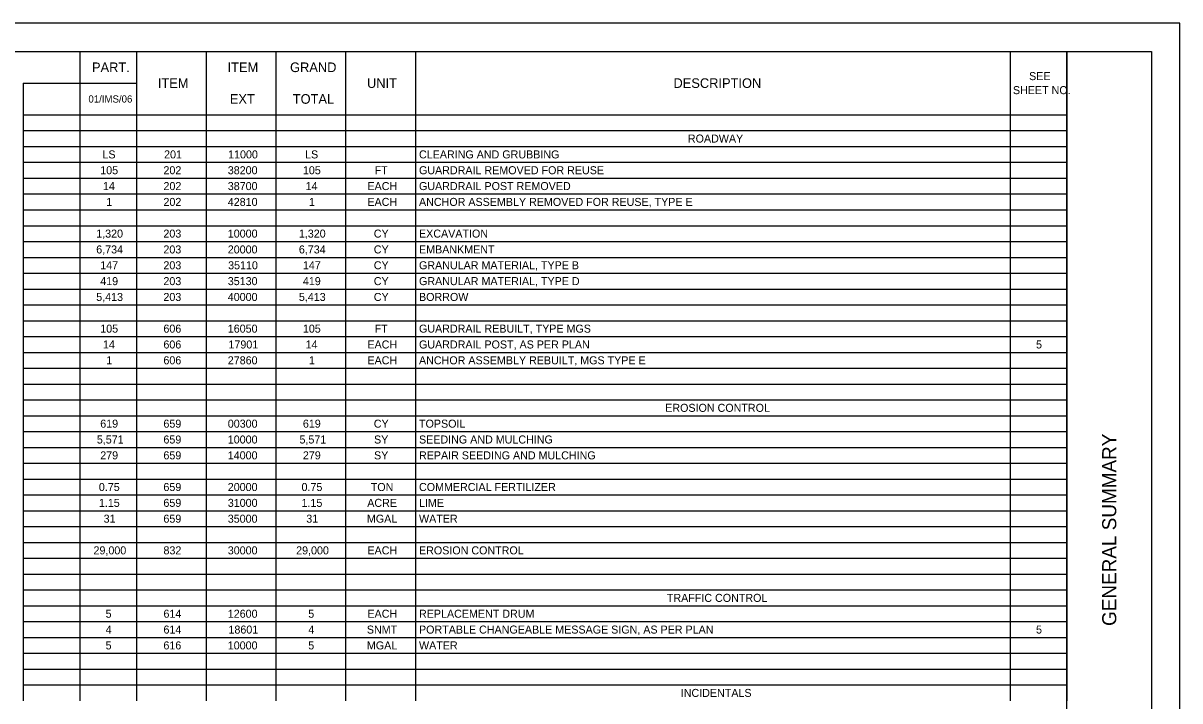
# Model space of a CAD drawing. Extents: x 0 to 34, y 0 to 22.
# Drawn here: x 13.53 to 34, y 10.02 to 22 of the extents above; entities that cross this region are included whole.
import ezdxf

# ---------------------------------------------------------------- set-up
doc = ezdxf.new("R2010")
doc.units = 0
for name, color, linetype in [('Default', 7, 'Continuous'), ('SH_Border', 7, 'Continuous'), ('SH_Cut_Line', 7, 'Continuous'), ('SH_Data', 7, 'Continuous')]:
    doc.layers.add(name, color=color, linetype=linetype)

msp = doc.modelspace()

# ---------------------------------------------------------------- linework, layer by layer
at = {"layer": 'Default'}
for p, q in [((13.531, 21.5), (15.536, 21.5)), ((14.533, 21.5), (14.533, 21.22)), ((15.536, 21.5), (32.001, 21.5)), ((15.536, 21.5), (15.536, 21.22)), ((16.77, 21.5), (16.77, 21.22)), ((18.004, 21.5), (18.004, 21.22)), ((19.237, 21.5), (19.237, 21.22)), ((20.471, 21.5), (20.471, 21.22)), ((30.998, 21.5), (30.998, 21.22)), ((32.001, 21.5), (32.001, 21.22)), ((14.533, 21.22), (14.533, 20.94)), ((15.536, 21.22), (15.536, 20.94)), ((16.77, 21.22), (16.77, 20.94)), ((18.004, 21.22), (18.004, 20.94)), ((19.237, 21.22), (19.237, 20.94)), ((20.471, 21.22), (20.471, 20.94)), ((30.998, 21.22), (30.998, 20.94)), ((32.001, 21.22), (32.001, 20.94)), ((13.531, 20.94), (15.536, 20.94)), ((13.531, 20.94), (13.531, 20.66)), ((14.533, 20.94), (14.533, 20.66)), ((15.536, 20.94), (15.536, 20.66)), ((16.77, 20.94), (16.77, 20.66)), ((18.004, 20.94), (18.004, 20.66)), ((19.237, 20.94), (19.237, 20.66)), ((20.471, 20.94), (20.471, 20.66)), ((30.998, 20.94), (30.998, 20.66)), ((32.001, 20.94), (32.001, 20.66)), ((13.531, 20.66), (13.531, 20.38)), ((14.533, 20.66), (14.533, 20.38)), ((15.536, 20.66), (15.536, 20.38)), ((16.77, 20.66), (16.77, 20.38)), ((18.004, 20.66), (18.004, 20.38)), ((19.237, 20.66), (19.237, 20.38)), ((20.471, 20.66), (20.471, 20.38)), ((30.998, 20.66), (30.998, 20.38)), ((32.001, 20.66), (32.001, 20.38)), ((13.531, 20.38), (15.536, 20.38)), ((13.531, 20.38), (13.531, 20.1)), ((14.533, 20.38), (14.533, 20.1)), ((15.536, 20.38), (32.001, 20.38)), ((15.536, 20.38), (15.536, 20.1)), ((16.77, 20.38), (16.77, 20.1)), ((18.004, 20.38), (18.004, 20.1)), ((19.237, 20.38), (19.237, 20.1)), ((20.471, 20.38), (20.471, 20.1)), ((30.998, 20.38), (30.998, 20.1)), ((32.001, 20.38), (32.001, 20.1)), ((13.531, 20.1), (15.536, 20.1)), ((13.531, 20.1), (13.531, 18.7)), ((14.533, 20.1), (14.533, 18.7)), ((15.536, 20.1), (32.001, 20.1)), ((15.536, 20.1), (15.536, 18.7)), ((16.77, 20.1), (16.77, 18.7)), ((18.004, 20.1), (18.004, 18.7)), ((19.237, 20.1), (19.237, 18.7)), ((20.471, 20.1), (20.471, 18.7)), ((30.998, 20.1), (30.998, 18.7)), ((32.001, 20.1), (32.001, 18.7)), ((13.531, 19.82), (15.536, 19.82)), ((15.536, 19.82), (32.001, 19.82)), ((13.531, 19.54), (15.536, 19.54)), ((15.536, 19.54), (32.001, 19.54)), ((13.531, 19.26), (15.536, 19.26)), ((15.536, 19.26), (32.001, 19.26)), ((13.531, 18.98), (15.536, 18.98)), ((15.536, 18.98), (32.001, 18.98)), ((13.531, 18.7), (15.536, 18.7)), ((13.531, 18.7), (13.531, 18.14)), ((14.533, 18.7), (14.533, 18.14)), ((15.536, 18.7), (32.001, 18.7)), ((15.536, 18.7), (15.536, 18.14)), ((16.77, 18.7), (16.77, 18.14)), ((18.004, 18.7), (18.004, 18.14)), ((19.237, 18.7), (19.237, 18.14)), ((20.471, 18.7), (20.471, 18.14)), ((30.998, 18.7), (30.998, 18.14)), ((32.001, 18.7), (32.001, 18.14)), ((13.531, 18.42), (15.536, 18.42)), ((15.536, 18.42), (32.001, 18.42)), ((13.531, 18.14), (15.536, 18.14)), ((13.531, 18.14), (13.531, 17.86)), ((14.533, 18.14), (14.533, 17.86)), ((15.536, 18.14), (32.001, 18.14)), ((15.536, 18.14), (15.536, 17.86)), ((16.77, 18.14), (16.77, 17.86)), ((18.004, 18.14), (18.004, 17.86)), ((19.237, 18.14), (19.237, 17.86)), ((20.471, 18.14), (20.471, 17.86)), ((30.998, 18.14), (30.998, 17.86)), ((32.001, 18.14), (32.001, 17.86)), ((13.531, 17.86), (15.536, 17.86)), ((13.531, 17.86), (13.531, 17.58)), ((14.533, 17.86), (14.533, 17.58)), ((15.536, 17.86), (32.001, 17.86)), ((15.536, 17.86), (15.536, 17.58)), ((16.77, 17.86), (16.77, 17.58)), ((18.004, 17.86), (18.004, 17.58)), ((19.237, 17.86), (19.237, 17.58)), ((20.471, 17.86), (20.471, 17.58)), ((30.998, 17.86), (30.998, 17.58)), ((32.001, 17.86), (32.001, 17.58)), ((13.531, 17.58), (15.536, 17.58)), ((13.531, 17.58), (13.531, 17.3)), ((14.533, 17.58), (14.533, 17.3)), ((15.536, 17.58), (32.001, 17.58)), ((15.536, 17.58), (15.536, 17.3)), ((16.77, 17.58), (16.77, 17.3)), ((18.004, 17.58), (18.004, 17.3)), ((19.237, 17.58), (19.237, 17.3)), ((20.471, 17.58), (20.471, 17.3)), ((30.998, 17.58), (30.998, 17.3)), ((32.001, 17.58), (32.001, 17.3)), ((13.531, 17.3), (15.536, 17.3)), ((13.531, 17.3), (13.531, 17.02)), ((14.533, 17.3), (14.533, 17.02)), ((15.536, 17.3), (32.001, 17.3)), ((15.536, 17.3), (15.536, 17.02)), ((16.77, 17.3), (16.77, 17.02)), ((18.004, 17.3), (18.004, 17.02)), ((19.237, 17.3), (19.237, 17.02)), ((20.471, 17.3), (20.471, 17.02)), ((30.998, 17.3), (30.998, 17.02)), ((32.001, 17.3), (32.001, 17.02)), ((13.531, 17.02), (15.536, 17.02)), ((13.531, 17.02), (13.531, 16.74)), ((14.533, 17.02), (14.533, 16.74)), ((15.536, 17.02), (32.001, 17.02)), ((15.536, 17.02), (15.536, 16.74)), ((16.77, 17.02), (16.77, 16.74)), ((18.004, 17.02), (18.004, 16.74)), ((19.237, 17.02), (19.237, 16.74)), ((20.471, 17.02), (20.471, 16.74)), ((30.998, 17.02), (30.998, 16.74)), ((32.001, 17.02), (32.001, 16.74)), ((13.531, 16.74), (15.536, 16.74)), ((13.531, 16.74), (13.531, 16.18)), ((14.533, 16.74), (14.533, 16.18)), ((15.536, 16.74), (32.001, 16.74)), ((15.536, 16.74), (15.536, 16.18)), ((16.77, 16.74), (16.77, 16.18)), ((18.004, 16.74), (18.004, 16.18)), ((19.237, 16.74), (19.237, 16.18)), ((20.471, 16.74), (20.471, 16.18)), ((30.998, 16.74), (30.998, 16.18)), ((32.001, 16.74), (32.001, 16.18)), ((13.531, 16.46), (15.536, 16.46)), ((15.536, 16.46), (32.001, 16.46)), ((13.531, 16.18), (15.536, 16.18)), ((13.531, 16.18), (13.531, 15.9)), ((14.533, 16.18), (14.533, 15.9)), ((15.536, 16.18), (32.001, 16.18)), ((15.536, 16.18), (15.536, 15.9)), ((16.77, 16.18), (16.77, 15.9)), ((18.004, 16.18), (18.004, 15.9)), ((19.237, 16.18), (19.237, 15.9)), ((20.471, 16.18), (20.471, 15.9)), ((30.998, 16.18), (30.998, 15.9)), ((32.001, 16.18), (32.001, 15.9)), ((13.531, 15.9), (15.536, 15.9)), ((13.531, 15.9), (13.531, 15.62)), ((14.533, 15.9), (14.533, 15.62)), ((15.536, 15.9), (32.001, 15.9)), ((15.536, 15.9), (15.536, 15.62)), ((16.77, 15.9), (16.77, 15.62)), ((18.004, 15.9), (18.004, 15.62)), ((19.237, 15.9), (19.237, 15.62)), ((20.471, 15.9), (20.471, 15.62)), ((30.998, 15.9), (30.998, 15.62)), ((32.001, 15.9), (32.001, 15.62)), ((13.531, 15.62), (15.536, 15.62)), ((13.531, 15.62), (13.531, 15.34)), ((14.533, 15.62), (14.533, 15.34)), ((15.536, 15.62), (32.001, 15.62)), ((15.536, 15.62), (15.536, 15.34)), ((16.77, 15.62), (16.77, 15.34)), ((18.004, 15.62), (18.004, 15.34)), ((19.237, 15.62), (19.237, 15.34)), ((20.471, 15.62), (20.471, 15.34)), ((30.998, 15.62), (30.998, 15.34)), ((32.001, 15.62), (32.001, 15.34)), ((13.531, 15.34), (15.536, 15.34)), ((13.531, 15.34), (13.531, 14.78)), ((14.533, 15.34), (14.533, 14.78)), ((15.536, 15.34), (32.001, 15.34)), ((15.536, 15.34), (15.536, 14.78)), ((16.77, 15.34), (16.77, 14.78)), ((18.004, 15.34), (18.004, 14.78)), ((19.237, 15.34), (19.237, 14.78)), ((20.471, 15.34), (20.471, 14.78)), ((30.998, 15.34), (30.998, 14.78)), ((32.001, 15.34), (32.001, 14.78)), ((13.531, 15.06), (15.536, 15.06)), ((15.536, 15.06), (32.001, 15.06)), ((13.531, 14.78), (15.536, 14.78)), ((13.531, 14.78), (13.531, 14.5)), ((14.533, 14.78), (14.533, 14.5)), ((15.536, 14.78), (32.001, 14.78)), ((15.536, 14.78), (15.536, 14.5)), ((16.77, 14.78), (16.77, 14.5)), ((18.004, 14.78), (18.004, 14.5)), ((19.237, 14.78), (19.237, 14.5)), ((20.471, 14.78), (20.471, 14.5)), ((30.998, 14.78), (30.998, 14.5)), ((32.001, 14.78), (32.001, 14.5)), ((13.531, 14.5), (15.536, 14.5)), ((13.531, 14.5), (13.531, 14.22)), ((14.533, 14.5), (14.533, 14.22)), ((15.536, 14.5), (32.001, 14.5)), ((15.536, 14.5), (15.536, 14.22)), ((16.77, 14.5), (16.77, 14.22)), ((18.004, 14.5), (18.004, 14.22)), ((19.237, 14.5), (19.237, 14.22)), ((20.471, 14.5), (20.471, 14.22)), ((30.998, 14.5), (30.998, 14.22)), ((32.001, 14.5), (32.001, 14.22)), ((13.531, 14.22), (15.536, 14.22)), ((13.531, 14.22), (13.531, 13.94)), ((14.533, 14.22), (14.533, 13.94)), ((15.536, 14.22), (32.001, 14.22)), ((15.536, 14.22), (15.536, 13.94)), ((16.77, 14.22), (16.77, 13.94)), ((18.004, 14.22), (18.004, 13.94)), ((19.237, 14.22), (19.237, 13.94)), ((20.471, 14.22), (20.471, 13.94)), ((30.998, 14.22), (30.998, 13.94)), ((32.001, 14.22), (32.001, 13.94)), ((13.531, 13.94), (15.536, 13.94)), ((13.531, 13.94), (13.531, 11.7)), ((14.533, 13.94), (14.533, 11.7)), ((15.536, 13.94), (32.001, 13.94)), ((15.536, 13.94), (15.536, 11.7)), ((16.77, 13.94), (16.77, 11.7)), ((18.004, 13.94), (18.004, 11.7)), ((19.237, 13.94), (19.237, 11.7)), ((20.471, 13.94), (20.471, 11.7)), ((30.998, 13.94), (30.998, 11.7)), ((32.001, 13.94), (32.001, 11.7)), ((13.531, 13.66), (15.536, 13.66)), ((15.536, 13.66), (32.001, 13.66)), ((13.531, 13.38), (15.536, 13.38)), ((15.536, 13.38), (32.001, 13.38)), ((13.531, 13.1), (15.536, 13.1)), ((15.536, 13.1), (32.001, 13.1)), ((13.531, 12.82), (15.536, 12.82)), ((15.536, 12.82), (32.001, 12.82)), ((13.531, 12.54), (15.536, 12.54)), ((15.536, 12.54), (32.001, 12.54)), ((13.531, 12.26), (15.536, 12.26)), ((15.536, 12.26), (32.001, 12.26)), ((13.531, 11.98), (15.536, 11.98)), ((15.536, 11.98), (32.001, 11.98)), ((13.531, 11.7), (15.536, 11.7)), ((13.531, 11.7), (13.531, 11.42)), ((14.533, 11.7), (14.533, 11.42)), ((15.536, 11.7), (32.001, 11.7)), ((15.536, 11.7), (15.536, 11.42)), ((16.77, 11.7), (16.77, 11.42)), ((18.004, 11.7), (18.004, 11.42)), ((19.237, 11.7), (19.237, 11.42)), ((20.471, 11.7), (20.471, 11.42)), ((30.998, 11.7), (30.998, 11.42)), ((32.001, 11.7), (32.001, 11.42)), ((13.531, 11.42), (15.536, 11.42)), ((13.531, 11.42), (13.531, 10.3)), ((14.533, 11.42), (14.533, 10.3)), ((15.536, 11.42), (32.001, 11.42)), ((15.536, 11.42), (15.536, 10.3)), ((16.77, 11.42), (16.77, 10.3)), ((18.004, 11.42), (18.004, 10.3)), ((19.237, 11.42), (19.237, 10.3)), ((20.471, 11.42), (20.471, 10.3)), ((30.998, 11.42), (30.998, 10.3)), ((32.001, 11.42), (32.001, 10.3)), ((13.531, 11.14), (15.536, 11.14)), ((15.536, 11.14), (32.001, 11.14)), ((13.531, 10.86), (15.536, 10.86)), ((15.536, 10.86), (32.001, 10.86)), ((13.531, 10.58), (15.536, 10.58)), ((15.536, 10.58), (32.001, 10.58)), ((13.531, 10.3), (15.536, 10.3)), ((13.531, 10.3), (13.531, 10.02)), ((14.533, 10.3), (14.533, 10.02)), ((15.536, 10.3), (32.001, 10.3)), ((15.536, 10.3), (15.536, 10.02)), ((16.77, 10.3), (16.77, 10.02)), ((18.004, 10.3), (18.004, 10.02)), ((19.237, 10.3), (19.237, 10.02)), ((20.471, 10.3), (20.471, 10.02)), ((30.998, 10.3), (30.998, 10.02)), ((32.001, 10.3), (32.001, 10.02))]:
    msp.add_line(p, q, dxfattribs=at)
at = {"layer": 'SH_Border'}
msp.add_line((32, 0.5), (32, 21.5), dxfattribs=at)
msp.add_lwpolyline([(1.5, 21.5), (33.5, 21.5), (33.5, 0.5), (1.5, 0.5)], close=True, dxfattribs=at)
at = {"layer": 'SH_Cut_Line'}
msp.add_lwpolyline([(0, 0), (34, 0), (34, 22), (0, 22)], close=True, dxfattribs=at)

# ---------------------------------------------------------------- texts
at = {"layer": 'Default'}
for s, height, p in [('PART.', 0.17, (14.749, 21.135)), ('ITEM', 0.17, (17.148, 21.135)), ('GRAND', 0.17, (18.254, 21.135)), ('SEE ', 0.1417, (31.332, 20.993)), ('ITEM', 0.17, (15.914, 20.855)), ('UNIT', 0.17, (19.616, 20.855)), ('DESCRIPTION', 0.17, (25.039, 20.855)), ('SHEET NO.', 0.1417, (31.046, 20.745)), ('01/IMS/06', 0.1275, (14.686, 20.596)), ('EXT', 0.17, (17.188, 20.575)), ('TOTAL', 0.17, (18.302, 20.575)), ('ROADWAY', 0.1417, (25.294, 19.889)), ('LS', 0.1417, (14.934, 19.609)), ('201', 0.1417, (16.025, 19.609)), ('11000', 0.1417, (17.158, 19.609)), ('LS', 0.1417, (18.52, 19.609)), ('CLEARING AND GRUBBING', 0.14167, (20.536, 19.609)), ('105', 0.1417, (14.895, 19.329)), ('202', 0.1417, (16.014, 19.329)), ('38200', 0.1417, (17.152, 19.329)), ('105', 0.1417, (18.481, 19.329)), ('FT', 0.1417, (19.751, 19.329)), ('GUARDRAIL REMOVED FOR REUSE', 0.14167, (20.536, 19.329)), ('14', 0.1417, (14.943, 19.049)), ('202', 0.1417, (16.014, 19.049)), ('38700', 0.1417, (17.152, 19.049)), ('14', 0.1417, (18.529, 19.049)), ('EACH', 0.1417, (19.623, 19.049)), ('GUARDRAIL POST REMOVED', 0.14167, (20.536, 19.049)), ('1', 0.142, (15.002, 18.769)), ('202', 0.1417, (16.014, 18.769)), ('42810', 0.1417, (17.152, 18.769)), ('1', 0.142, (18.589, 18.769)), ('EACH', 0.1417, (19.623, 18.769)), ('ANCHOR ASSEMBLY REMOVED FOR REUSE, TYPE E', 0.14167, (20.536, 18.769)), ('1,320', 0.1417, (14.824, 18.209)), ('203', 0.1417, (16.013, 18.209)), ('10000', 0.1417, (17.152, 18.209)), ('1,320', 0.1417, (18.41, 18.209)), ('CY', 0.1417, (19.736, 18.209)), ('EXCAVATION', 0.1417, (20.536, 18.209)), ('6,734', 0.1417, (14.824, 17.929)), ('203', 0.1417, (16.013, 17.929)), ('20000', 0.1417, (17.152, 17.929)), ('6,734', 0.1417, (18.41, 17.929)), ('CY', 0.1417, (19.736, 17.929)), ('EMBANKMENT', 0.1417, (20.536, 17.929)), ('147', 0.1417, (14.895, 17.649)), ('203', 0.1417, (16.013, 17.649)), ('35110', 0.1417, (17.158, 17.649)), ('147', 0.1417, (18.481, 17.649)), ('CY', 0.1417, (19.736, 17.649)), ('GRANULAR MATERIAL, TYPE B', 0.14167, (20.536, 17.649)), ('419', 0.1417, (14.895, 17.369)), ('203', 0.1417, (16.013, 17.369)), ('35130', 0.1417, (17.152, 17.369)), ('419', 0.1417, (18.481, 17.369)), ('CY', 0.1417, (19.736, 17.369)), ('GRANULAR MATERIAL, TYPE D', 0.14167, (20.536, 17.369)), ('5,413', 0.1417, (14.824, 17.089)), ('203', 0.1417, (16.013, 17.089)), ('40000', 0.1417, (17.152, 17.089)), ('5,413', 0.1417, (18.41, 17.089)), ('CY', 0.1417, (19.736, 17.089)), ('BORROW', 0.1417, (20.536, 17.089)), ('105', 0.1417, (14.895, 16.529)), ('606', 0.1417, (16.013, 16.529)), ('16050', 0.1417, (17.152, 16.529)), ('105', 0.1417, (18.481, 16.529)), ('FT', 0.1417, (19.751, 16.529)), ('GUARDRAIL REBUILT, TYPE MGS', 0.14167, (20.536, 16.529)), ('14', 0.1417, (14.943, 16.249)), ('606', 0.1417, (16.013, 16.249)), ('17901', 0.1417, (17.164, 16.249)), ('14', 0.1417, (18.529, 16.249)), ('EACH', 0.1417, (19.623, 16.249)), ('GUARDRAIL POST, AS PER PLAN', 0.14167, (20.536, 16.249)), ('5', 0.142, (31.455, 16.249)), ('1', 0.142, (15.002, 15.969)), ('606', 0.1417, (16.013, 15.969)), ('27860', 0.1417, (17.152, 15.969)), ('1', 0.142, (18.589, 15.969)), ('EACH', 0.1417, (19.623, 15.969)), ('ANCHOR ASSEMBLY REBUILT, MGS TYPE E', 0.14167, (20.536, 15.969)), ('EROSION CONTROL', 0.14167, (24.893, 15.129)), ('619', 0.1417, (14.895, 14.849)), ('659', 0.1417, (16.013, 14.849)), ('00300', 0.1417, (17.152, 14.849)), ('619', 0.1417, (18.481, 14.849)), ('CY', 0.1417, (19.736, 14.849)), ('TOPSOIL', 0.1417, (20.536, 14.849)), ('5,571', 0.1417, (14.835, 14.569)), ('659', 0.1417, (16.013, 14.569)), ('10000', 0.1417, (17.152, 14.569)), ('5,571', 0.1417, (18.421, 14.569)), ('SY', 0.1417, (19.74, 14.569)), ('SEEDING AND MULCHING', 0.14167, (20.536, 14.569)), ('279', 0.1417, (14.895, 14.289)), ('659', 0.1417, (16.013, 14.289)), ('14000', 0.1417, (17.152, 14.289)), ('279', 0.1417, (18.481, 14.289)), ('SY', 0.1417, (19.74, 14.289)), ('REPAIR SEEDING AND MULCHING', 0.14167, (20.536, 14.289)), ('0.75', 0.1417, (14.871, 13.729)), ('659', 0.1417, (16.013, 13.729)), ('20000', 0.1417, (17.152, 13.729)), ('0.75', 0.1417, (18.457, 13.729)), ('TON', 0.1417, (19.682, 13.729)), ('COMMERCIAL FERTILIZER', 0.14167, (20.536, 13.729)), ('1.15', 0.1417, (14.871, 13.449)), ('659', 0.1417, (16.013, 13.449)), ('31000', 0.1417, (17.152, 13.449)), ('1.15', 0.1417, (18.457, 13.449)), ('ACRE', 0.1417, (19.62, 13.449)), ('LIME', 0.1417, (20.536, 13.449)), ('31', 0.1417, (14.955, 13.169)), ('659', 0.1417, (16.013, 13.169)), ('35000', 0.1417, (17.152, 13.169)), ('31', 0.1417, (18.541, 13.169)), ('MGAL', 0.1417, (19.614, 13.169)), ('WATER', 0.1417, (20.536, 13.169)), ('29,000', 0.1417, (14.776, 12.609)), ('832', 0.1417, (16.014, 12.609)), ('30000', 0.1417, (17.152, 12.609)), ('29,000', 0.1417, (18.362, 12.609)), ('EACH', 0.1417, (19.623, 12.609)), ('EROSION CONTROL', 0.14167, (20.536, 12.609)), ('TRAFFIC CONTROL', 0.14167, (24.922, 11.769)), ('5', 0.142, (14.99, 11.489)), ('614', 0.1417, (16.014, 11.489)), ('12600', 0.1417, (17.152, 11.489)), ('5', 0.142, (18.576, 11.489)), ('EACH', 0.1417, (19.623, 11.489)), ('REPLACEMENT DRUM', 0.14167, (20.536, 11.489)), ('4', 0.142, (14.991, 11.209)), ('614', 0.1417, (16.014, 11.209)), ('18601', 0.1417, (17.164, 11.209)), ('4', 0.142, (18.577, 11.209)), ('SNMT', 0.1417, (19.613, 11.209)), ('PORTABLE CHANGEABLE MESSAGE SIGN, AS PER PLAN', 0.14167, (20.536, 11.209)), ('5', 0.142, (31.455, 11.209)), ('5', 0.142, (14.99, 10.929)), ('616', 0.1417, (16.013, 10.929)), ('10000', 0.1417, (17.152, 10.929)), ('5', 0.142, (18.576, 10.929)), ('MGAL', 0.1417, (19.614, 10.929)), ('WATER', 0.1417, (20.536, 10.929)), ('INCIDENTALS', 0.14167, (25.168, 10.089))]:
    msp.add_text(s, height=height, dxfattribs=at).set_placement(p)
at = {"layer": 'SH_Data'}
msp.add_text('GENERAL SUMMARY', height=0.25, rotation=90, dxfattribs=at).set_placement((32.875, 11.344))

doc.saveas('drawing.dxf')
